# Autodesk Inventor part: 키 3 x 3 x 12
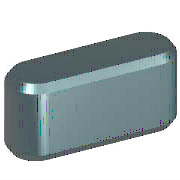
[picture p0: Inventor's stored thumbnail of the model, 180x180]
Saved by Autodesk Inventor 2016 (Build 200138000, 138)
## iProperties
Created: 2012-02
Part Number: 키 3 x 3 x 12
Material: 강철, 연강
Description: 키 및 해당 키홈
Document SubType Name: Modeling
Standard: KS B 1311
Designer: mduedu
Standards Organization: KS
Language: ko-KR
Size Designation: 3 x 3 x 12
Categories: <MemberInstance><Categories><Category DisplayName="샤프트 부품" InternalName="7f7aeb1f-a693-4053-b835-cee3144e0d98" Mnemonic="SHFT"><Category DisplayName="키" Interna
Density: 1 g/cm^3
Appearance: 노란색
IsCustomPart: 1
Author: mduedu
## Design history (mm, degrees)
workplane "Work Plane1"
workplane "Work Plane2"
sketch "스케치1"
  geometry: L1 (1.5, 1.5)-(10.5, 1.5); L2 (10.5, -1.5)-(1.5, -1.5); L3 (0, 9.4)-(0, -7.4) reference; L4 (-5, 0)-(30, 0) reference; L5 (12, 0)-(12, 7); A1 r 1.5 centre (1.5, 0) between (1.5, 1.5) and (1.5, -1.5); A2 r 1.5 centre (10.5, 0) between (10.5, -1.5) and (10.5, 1.5)
  constraints: 6 end point, 5 point on circle, 4 tangent, 3 point on line, 2 centre point, 1 horizontal, 1 parallel, 1 perpendicular
  dimensions: "d0" = 1.5 radius of A1 (= 0.5 x PB); "d13" = 1.5 radius of A2 (= 0.5 x PB); "d14" = 12 distance between parallel lines of L5 L3 (= NLG)
extrude "본체1" new body sketch "스케치1" taper "d3" = 0 deg; stored distance "d4" = 10
workplane "Work Plane3"
body "Solid1"
chamfer "모따기1" distance "d8" = 0.25 (= PHH); stored, may be unused: second distance "d9" = 0.25 (= PHH), angle "d15" = 45 deg
other parameters: "d1" = -1.8 (= -PNT), "d2" = 1.2 (= PH - PNT), "NLG" = 12 [user parameter; used in 3 equation terms], "PB" = 3 [user parameter; used in 2 equation terms], "PNT" = 1.8 [user parameter; used in 2 equation terms], "PH" = 3 [user parameter; used in 1 equation term], "PHH" = 0.25 [user parameter; used in 2 equation terms], "d10" = 0, "d16" = 0, "d17" = 0, "d18" = 0, "WDMIN" = 8 [user parameter], "PLB2" = 12 (= NLG) [user parameter], "PLB1" = 12 (= NLG) [user parameter], "RR" = 0.08 [user parameter], "PUEB" = 1.4 [user parameter]
